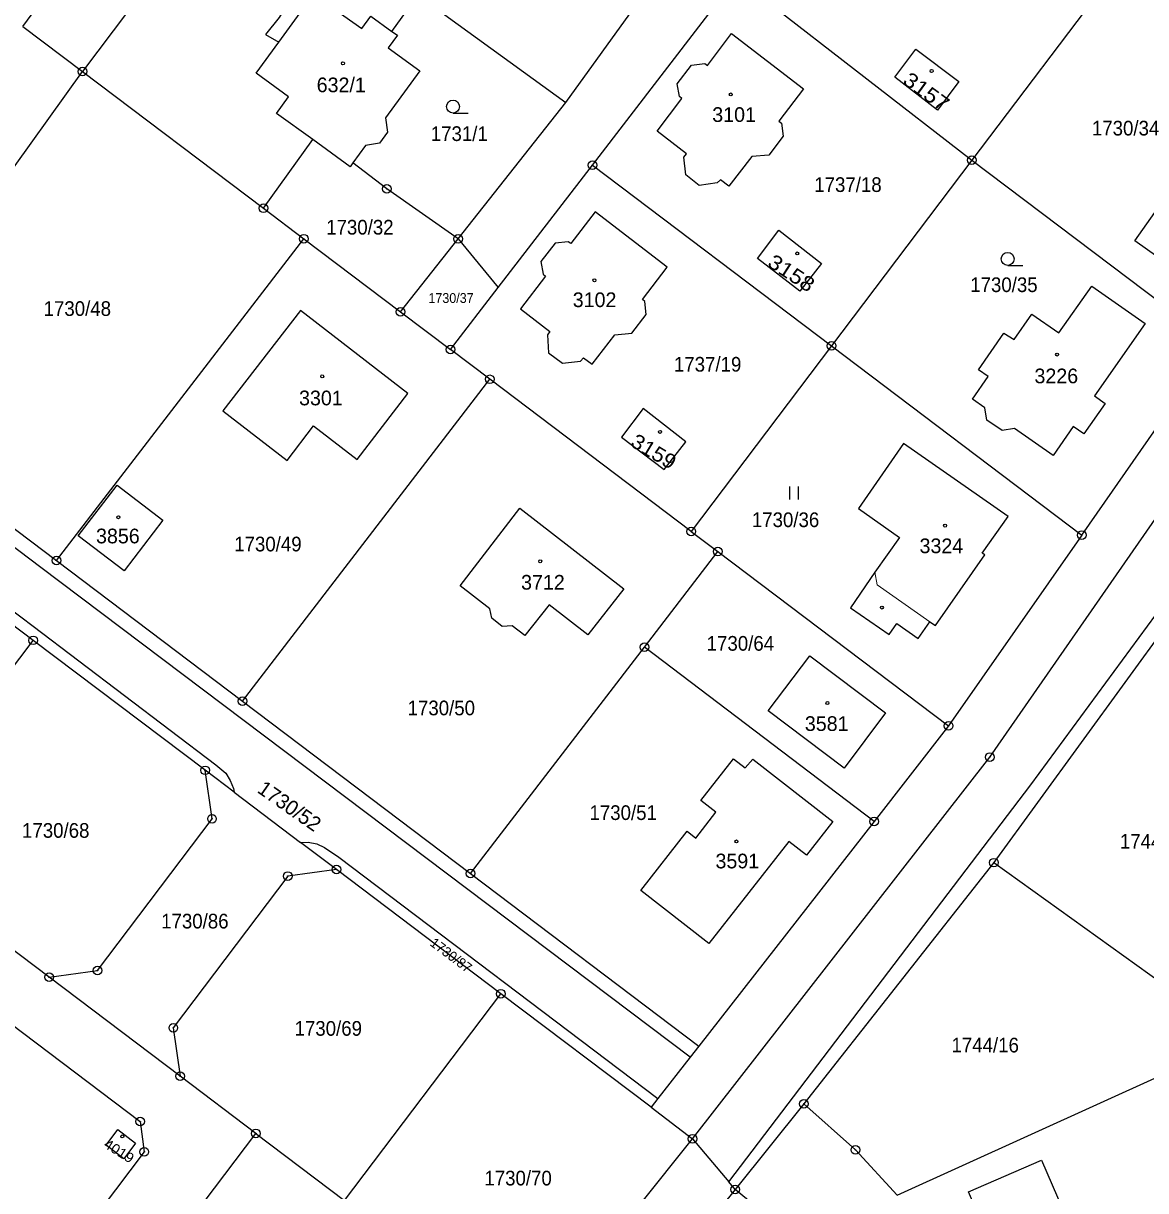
# Model space of a CAD drawing. Extents: x -679733 to -673243, y -1075091 to -1066557.
# Drawn here: x -676982.3 to -676852.3, y -1072340.3 to -1072205.2 of the extents above; entities that cross this region are included whole.
import ezdxf
from ezdxf.enums import TextEntityAlignment as Align

# ---------------------------------------------------------------- set-up
doc = ezdxf.new("R2010")
doc.units = 0
doc.header["$LTSCALE"] = 0.68
for name, color, linetype, lineweight in [('1', 7, 'Continuous', 25), ('3', 7, 'Continuous', 25), ('4', 7, 'Continuous', 13), ('5', 7, 'Continuous', 25), ('8', 7, 'Continuous', 25)]:
    doc.layers.add(name, color=color, linetype=linetype, lineweight=lineweight)
doc.layers.add('2', color=7, linetype='Continuous')

msp = doc.modelspace()

# ---------------------------------------------------------------- linework, layer by layer
at = {"layer": '1'}
for p, q in [((-676899.68, -1072199.86), (-676872.43, -1072221.01)), ((-676934.58, -1072203.37), (-676919.44, -1072214.32)), ((-676982.32, -1072205.52), (-676975.41, -1072210.74)), ((-677002.87, -1072248.9), (-676975.41, -1072210.74)), ((-676931.93, -1072230.12), (-676919.44, -1072214.32)), ((-676916.37, -1072221.57), (-676888.67, -1072242.5)), ((-676954.45, -1072226.57), (-676949.79, -1072230.09)), ((-676888.67, -1072242.5), (-676904.92, -1072263.99)), ((-676904.92, -1072263.99), (-676928.25, -1072246.37)), ((-676961.22, -1072291.64), (-676981.14, -1072276.59)), ((-676883.74, -1072297.55), (-676910.35, -1072277.39)), ((-676956.9, -1072283.63), (-676930.48, -1072303.58)), ((-676957.87, -1072294.17), (-676961.22, -1072291.64)), ((-676946.01, -1072303.12), (-676950.18, -1072299.98)), ((-676869.87, -1072302.33), (-676891.88, -1072330.24)), ((-676930.48, -1072303.58), (-676904.04, -1072323.56)), ((-676909.57, -1072330.65), (-676926.98, -1072317.5)), ((-676891.88, -1072330.24), (-676899.84, -1072340.16)), ((-676955.34, -1072333.67), (-676945.08, -1072341.44)), ((-676904.77, -1072334.29), (-676900.59, -1072339.27)), ((-676899.84, -1072340.16), (-676900.59, -1072339.27))]:
    msp.add_line(p, q, dxfattribs=at)
for points in [[(-676919.44, -1072214.32), (-676899.4, -1072186.54), (-676904.51, -1072167.26)], [(-676982.32, -1072205.52), (-676964.73, -1072181.57), (-676957.44, -1072186.84), (-676936.58, -1072201.92), (-676934.58, -1072203.37)], [(-676957.44, -1072186.84), (-676975.41, -1072210.74), (-676954.45, -1072226.57), (-676948.76, -1072218.62)], [(-676904.77, -1072334.29), (-676870.34, -1072290.1), (-676818.72, -1072215.8), (-676800.09, -1072189.36)], [(-676937.89, -1072203.74), (-676947.59, -1072196.14), (-676952.65, -1072204.47), (-676954.21, -1072206.43), (-676952.7, -1072207.35)], [(-676931.93, -1072230.12), (-676927.27, -1072235.75), (-676916.37, -1072221.57), (-676899.68, -1072199.86)], [(-676952.7, -1072207.35), (-676948.66, -1072201.76), (-676943.09, -1072205.77), (-676942.03, -1072204.31), (-676939.58, -1072206.09), (-676937.89, -1072203.74)], [(-676939.58, -1072206.09), (-676938.96, -1072206.54), (-676940.01, -1072207.99), (-676936.36, -1072210.64), (-676940.32, -1072216.11), (-676940.09, -1072217.74), (-676941.03, -1072219.03), (-676942.65, -1072219.3), (-676944.1, -1072221.31)], [(-676948.76, -1072218.62), (-676952.95, -1072215.6), (-676951.55, -1072213.67), (-676955.29, -1072210.94), (-676952.7, -1072207.35)], [(-676944.1, -1072221.31), (-676944.42, -1072221.76), (-676948.76, -1072218.62)], [(-676872.43, -1072221.01), (-676888.67, -1072242.5), (-676859.7, -1072264.4), (-676844.27, -1072242.28)], [(-676931.93, -1072230.12), (-676940.17, -1072224.32), (-676944.1, -1072221.31)], [(-677002.87, -1072248.9), (-676978.44, -1072267.35), (-676949.79, -1072230.09)], [(-676949.79, -1072230.09), (-676938.6, -1072238.55), (-676931.93, -1072230.12)], [(-676900.59, -1072339.27), (-676865.59, -1072293.33), (-676821.22, -1072232.97)], [(-676938.6, -1072238.55), (-676932.8, -1072242.93), (-676927.27, -1072235.75)], [(-676978.44, -1072267.35), (-676956.9, -1072283.63), (-676928.25, -1072246.37), (-676932.8, -1072242.93)], [(-676905.06, -1072324.86), (-676980.24, -1072268.15), (-677003.21, -1072250.78), (-677011.13, -1072244.77)], [(-677014.68, -1072249.6), (-677006.87, -1072255.49), (-676981.13, -1072274.94), (-676959.99, -1072291), (-676958.83, -1072291.96), (-676958.3, -1072292.81), (-676957.95, -1072293.75), (-676957.87, -1072294.17), (-676950.18, -1072299.98)], [(-677028.33, -1072278.52), (-676999.23, -1072300.52), (-676981.14, -1072276.59), (-677009.25, -1072255.35)], [(-676904.92, -1072263.99), (-676901.84, -1072266.32), (-676875.12, -1072286.5)], [(-676859.7, -1072264.4), (-676875.12, -1072286.5), (-676883.74, -1072297.55), (-676904.04, -1072323.56), (-676905.06, -1072324.86), (-676908.8, -1072329.65), (-676909.57, -1072330.65), (-676904.77, -1072334.29)], [(-676930.48, -1072303.58), (-676910.35, -1072277.39), (-676901.84, -1072266.32)], [(-676844.59, -1072267.57), (-676869.87, -1072302.33), (-676850.33, -1072316.37)], [(-676979.28, -1072315.59), (-676973.68, -1072314.81), (-676960.42, -1072297.25), (-676961.22, -1072291.64)], [(-677027.68, -1072429.42), (-677013.21, -1072410.27), (-676998.74, -1072391.12), (-676984.27, -1072371.97), (-676969.81, -1072352.82), (-676955.34, -1072333.67), (-676964.12, -1072327.04), (-676979.28, -1072315.59), (-676999.23, -1072300.52), (-677013.7, -1072319.67), (-677028.16, -1072338.82), (-677042.63, -1072357.97), (-677057.1, -1072377.12), (-677060.11, -1072381.11), (-677041.76, -1072394.98)], [(-676950.18, -1072299.98), (-676949.27, -1072299.96), (-676948.29, -1072300.16), (-676947.39, -1072300.57), (-676945.74, -1072301.71), (-676908.8, -1072329.65)], [(-676946.01, -1072303.12), (-676951.64, -1072303.88), (-676964.9, -1072321.44), (-676964.12, -1072327.04)], [(-676945.08, -1072341.44), (-676926.98, -1072317.5), (-676946.01, -1072303.12)], [(-677034.04, -1072358.2), (-676999.38, -1072312.31), (-676995.87, -1072311.82), (-676968.74, -1072332.31), (-676968.26, -1072335.81), (-677002.92, -1072381.7)], [(-676891.88, -1072330.24), (-676885.92, -1072335.57), (-676881.09, -1072340.82), (-676850.38, -1072326.91), (-676840.3, -1072323.62), (-676850.33, -1072316.37)], [(-676945.08, -1072341.44), (-676923.5, -1072357.73), (-676904.77, -1072334.29)], [(-676899.84, -1072340.16), (-676917.54, -1072362.22), (-676920.09, -1072365.43), (-676901.39, -1072381.05)], [(-676891.76, -1072389.1), (-676878.69, -1072384.73), (-676876.78, -1072380.9), (-676883.43, -1072361.01), (-676885.57, -1072356.35), (-676888.78, -1072351.13), (-676893.71, -1072345.23), (-676899.84, -1072340.16)]]:
    msp.add_lwpolyline(points, dxfattribs=at)
for points in [[(-676844.27, -1072242.28), (-676829.22, -1072220.7), (-676848.74, -1072205.36), (-676856.19, -1072199.51), (-676872.43, -1072221.01)], [(-676901.53, -1072223.27), (-676901.92, -1072223.61), (-676903.99, -1072223.94), (-676905.55, -1072222.71), (-676905.77, -1072220.66), (-676905.48, -1072220.26), (-676908.89, -1072217.63), (-676906.02, -1072213.86), (-676906.3, -1072213.62), (-676906.56, -1072212.15), (-676904.89, -1072210), (-676903.37, -1072209.8), (-676903.06, -1072210.02), (-676900.26, -1072206.35), (-676891.93, -1072212.75), (-676894.78, -1072216.47), (-676894.48, -1072216.72), (-676894.29, -1072218.2), (-676895.96, -1072220.4), (-676897.9, -1072220.58), (-676900.56, -1072224.01)], [(-676873.92, -1072211.88), (-676876.42, -1072215.19), (-676881.35, -1072211.4), (-676878.9, -1072208.15)], [(-676853.57, -1072230.33), (-676844.23, -1072217.11), (-676837.7, -1072221.73), (-676847.02, -1072234.95)], [(-676921.58, -1072241.22), (-676921.46, -1072243.29), (-676919.84, -1072244.51), (-676917.76, -1072244.27), (-676917.39, -1072243.87), (-676916.41, -1072244.6), (-676913.78, -1072241.23), (-676911.81, -1072241.02), (-676910.14, -1072238.87), (-676910.3, -1072237.35), (-676910.58, -1072237.12), (-676907.73, -1072233.39), (-676916.04, -1072226.98), (-676918.88, -1072230.64), (-676919.16, -1072230.44), (-676920.7, -1072230.61), (-676922.36, -1072232.73), (-676922.09, -1072234.21), (-676921.8, -1072234.44), (-676924.71, -1072238.2), (-676921.29, -1072240.84)], [(-676889.83, -1072232.95), (-676892.35, -1072236.18), (-676897.25, -1072232.37), (-676894.77, -1072229.1)], [(-676870.93, -1072249.66), (-676872.37, -1072248.67), (-676870.56, -1072246.05), (-676871.67, -1072245.26), (-676868.71, -1072241.01), (-676867.53, -1072241.76), (-676865.5, -1072238.84), (-676862.35, -1072240.99), (-676858.55, -1072235.58), (-676852.37, -1072239.9), (-676858.23, -1072248.3), (-676857, -1072249.16), (-676859.45, -1072252.68), (-676860.69, -1072251.83), (-676863.03, -1072255.19), (-676867.49, -1072252.07), (-676868.91, -1072252.31), (-676870.68, -1072251.08)], [(-676950.19, -1072238.42), (-676959.18, -1072250.03), (-676951.72, -1072255.78), (-676948.65, -1072251.77), (-676943.61, -1072255.64), (-676937.73, -1072248.01)], [(-676908.07, -1072256.82), (-676905.56, -1072253.61), (-676910.49, -1072249.76), (-676912.99, -1072253.05)], [(-676870.91, -1072266.7), (-676871.23, -1072266.48), (-676868.22, -1072262.25), (-676880.35, -1072253.8), (-676885.54, -1072261.32), (-676880.82, -1072264.69), (-676883.67, -1072268.69), (-676886.47, -1072272.81), (-676882, -1072275.9), (-676881.11, -1072274.65), (-676878.64, -1072276.36), (-676877.29, -1072274.43), (-676876.63, -1072274.89)], [(-676975.9, -1072264.49), (-676971.42, -1072258.62), (-676966.12, -1072262.67), (-676970.61, -1072268.54)], [(-676926.82, -1072274.99), (-676928, -1072274.03), (-676928.24, -1072272.95), (-676931.7, -1072270.27), (-676924.79, -1072261.29), (-676912.75, -1072270.63), (-676916.9, -1072275.97), (-676921.39, -1072272.46), (-676924.19, -1072276.03), (-676925.67, -1072274.92)], [(-676891.21, -1072278.38), (-676882.42, -1072285), (-676887.23, -1072291.4), (-676896.02, -1072284.77)], [(-676904.4, -1072299.48), (-676902.08, -1072296.5), (-676903.8, -1072295.15), (-676900.03, -1072290.31), (-676898.7, -1072291.34), (-676897.78, -1072290.34), (-676888.52, -1072297.55), (-676891.58, -1072301.47), (-676893.62, -1072299.88), (-676902.88, -1072311.7), (-676910.77, -1072305.54), (-676905.4, -1072298.69)], [(-676971.34, -1072333.24), (-676969.29, -1072334.79), (-676970.62, -1072336.61), (-676972.67, -1072335.03)], [(-676866.54, -1072354.96), (-676869.74, -1072347.57), (-676869.09, -1072347.28), (-676870.37, -1072344.36), (-676871.02, -1072344.64), (-676872.83, -1072340.44), (-676864.36, -1072336.78), (-676858.08, -1072351.31)]]:
    msp.add_lwpolyline(points, close=True, dxfattribs=at)
at = {"layer": '3'}
for p, q in [((-676932.513, -1072215.54), (-676930.763, -1072215.54)), ((-676868.283, -1072233.18), (-676866.533, -1072233.18)), ((-676893.521, -1072260.29), (-676893.521, -1072258.79)), ((-676892.52, -1072260.29), (-676892.52, -1072258.79))]:
    msp.add_line(p, q, dxfattribs=at)
for centre in [(-676932.5129, -1072214.7898), (-676868.2829, -1072232.4298)]:
    msp.add_circle(centre, 0.75, dxfattribs=at)
at = {"layer": '4'}
for p, q in [((-676883.67, -1072268.69), (-676883.4, -1072270.15)), ((-676883.4, -1072270.15), (-676877.29, -1072274.43))]:
    msp.add_line(p, q, dxfattribs=at)
at = {"layer": '5'}
for centre in [(-676945.2568, -1072209.7792), (-676877.0868, -1072210.6792), (-676900.3468, -1072213.3892), (-676892.6568, -1072231.7992), (-676916.1368, -1072234.9092), (-676862.5568, -1072243.4992), (-676947.6568, -1072246.0292), (-676908.5368, -1072252.4592), (-676971.2668, -1072262.3392), (-676875.5268, -1072263.3092), (-676922.4168, -1072267.4392), (-676882.8468, -1072272.7992), (-676889.1568, -1072283.8492), (-676899.6868, -1072299.8692), (-676970.8068, -1072334.0292)]:
    msp.add_circle(centre, 0.175, dxfattribs=at)
at = {"layer": '8'}
for centre, radius in [((-676975.41, -1072210.7399), 0.5), ((-676975.41, -1072210.7399), 0.0303), ((-676872.43, -1072221.0099), 0.5), ((-676872.43, -1072221.0099), 0.0303), ((-676916.37, -1072221.5699), 0.5), ((-676916.37, -1072221.5699), 0.0303), ((-676940.17, -1072224.3199), 0.5), ((-676940.17, -1072224.3199), 0.0303), ((-676954.45, -1072226.5699), 0.5), ((-676954.45, -1072226.5699), 0.0303), ((-676949.79, -1072230.0899), 0.5), ((-676949.79, -1072230.0899), 0.0303), ((-676931.93, -1072230.1199), 0.5), ((-676931.93, -1072230.1199), 0.0303), ((-676938.6, -1072238.5499), 0.5), ((-676938.6, -1072238.5499), 0.0303), ((-676932.8, -1072242.9299), 0.5), ((-676888.67, -1072242.4999), 0.5), ((-676888.67, -1072242.4999), 0.0303), ((-676932.8, -1072242.9299), 0.0303), ((-676928.25, -1072246.3699), 0.5), ((-676928.25, -1072246.3699), 0.0303), ((-676904.92, -1072263.9899), 0.5), ((-676904.92, -1072263.9899), 0.0303), ((-676859.7, -1072264.3999), 0.5), ((-676859.7, -1072264.3999), 0.0303), ((-676978.44, -1072267.3499), 0.5), ((-676901.84, -1072266.3199), 0.5), ((-676901.84, -1072266.3199), 0.0303), ((-676978.44, -1072267.3499), 0.0303), ((-676981.14, -1072276.5899), 0.5), ((-676981.14, -1072276.5899), 0.0303), ((-676910.35, -1072277.3899), 0.5), ((-676910.35, -1072277.3899), 0.0303), ((-676956.9, -1072283.6299), 0.5), ((-676956.9, -1072283.6299), 0.0303), ((-676875.12, -1072286.4999), 0.5), ((-676875.12, -1072286.4999), 0.0303), ((-676870.34, -1072290.0999), 0.5), ((-676961.22, -1072291.6399), 0.5), ((-676870.34, -1072290.0999), 0.0303), ((-676961.22, -1072291.6399), 0.0303), ((-676960.42, -1072297.2499), 0.5), ((-676960.42, -1072297.2499), 0.0303), ((-676883.74, -1072297.5499), 0.5), ((-676883.74, -1072297.5499), 0.0303), ((-676869.87, -1072302.3299), 0.5), ((-676951.64, -1072303.8799), 0.5), ((-676946.01, -1072303.1199), 0.5), ((-676946.01, -1072303.1199), 0.0303), ((-676930.48, -1072303.5799), 0.5), ((-676869.87, -1072302.3299), 0.0303), ((-676951.64, -1072303.8799), 0.0303), ((-676930.48, -1072303.5799), 0.0303), ((-676979.28, -1072315.5899), 0.5), ((-676979.28, -1072315.5899), 0.0303), ((-676973.68, -1072314.8099), 0.5), ((-676973.68, -1072314.8099), 0.0303), ((-676926.98, -1072317.4999), 0.5), ((-676926.98, -1072317.4999), 0.0303), ((-676964.9, -1072321.4399), 0.5), ((-676964.9, -1072321.4399), 0.0303), ((-676964.12, -1072327.0399), 0.5), ((-676964.12, -1072327.0399), 0.0303), ((-676891.88, -1072330.2399), 0.5), ((-676891.88, -1072330.2399), 0.0303), ((-676968.74, -1072332.3099), 0.5), ((-676968.74, -1072332.3099), 0.0303), ((-676955.34, -1072333.6699), 0.5), ((-676955.34, -1072333.6699), 0.0303), ((-676904.77, -1072334.2899), 0.5), ((-676904.77, -1072334.2899), 0.0303), ((-676968.26, -1072335.8099), 0.5), ((-676968.26, -1072335.8099), 0.0303), ((-676885.92, -1072335.5699), 0.5), ((-676885.92, -1072335.5699), 0.0303), ((-676899.84, -1072340.1599), 0.5), ((-676899.84, -1072340.1599), 0.0303)]:
    msp.add_circle(centre, radius, dxfattribs=at)

# ---------------------------------------------------------------- texts
at = {"layer": '2'}
for s, p in [('632/1', (-676948.3, -1072213.13)), ('3101', (-676902.49, -1072216.57)), ('3102', (-676918.65, -1072238.009)), ('3226', (-676865.18, -1072246.83)), ('3301', (-676950.34, -1072249.38)), ('3856', (-676973.85, -1072265.36)), ('3324', (-676878.49, -1072266.499)), ('3712', (-676924.63, -1072270.72)), ('3581', (-676891.77, -1072287.08)), ('3591', (-676902.12, -1072302.989))]:
    msp.add_text(s, height=1.7, dxfattribs=at).set_placement(p)
for s, rotation, width, p in [('3157', 324, 1.15, (-676880.549, -1072212.047)), ('3158', 327, 1.15, (-676896.222, -1072233.202)), ('3159', 329, 1.1, (-676912.087, -1072254.018))]:
    msp.add_text(s, height=1.7, rotation=rotation, dxfattribs=dict(at, width=width)).set_placement(p)
at = {"layer": '2', "width": 0.95}
for s, height, p in [('1730/34', 1.7, (-676858.53, -1072218.14)), ('1731/1', 1.7, (-676935.09, -1072218.779)), ('1737/18', 1.7, (-676890.68, -1072224.68)), ('1730/32', 1.7, (-676947.2, -1072229.61)), ('1730/35', 1.7, (-676872.62, -1072236.269)), ('1730/37', 1.14, (-676935.36, -1072237.53)), ('1730/48', 1.7, (-676979.92, -1072239.029)), ('1737/19', 1.7, (-676906.93, -1072245.479)), ('1730/36', 1.7, (-676897.91, -1072263.479)), ('1730/49', 1.7, (-676957.85, -1072266.29)), ('1730/64', 1.7, (-676903.14, -1072277.79)), ('1730/50', 1.7, (-676937.77, -1072285.269)), ('1730/51', 1.7, (-676916.71, -1072297.39)), ('1730/68', 1.7, (-676982.42, -1072299.45)), ('1744/15', 1.7, (-676855.29, -1072300.72)), ('1730/86', 1.7, (-676966.31, -1072309.95)), ('1730/69', 1.7, (-676950.86, -1072322.37)), ('1744/16', 1.7, (-676874.79, -1072324.3)), ('1730/70', 1.7, (-676928.88, -1072339.7))]:
    msp.add_text(s, height=height, dxfattribs=at).set_placement(p)
at = {"layer": '2'}
for s, height, rotation, p in [('1730/52', 1.7, 325, (-676955.297, -1072294.116)), ('1730/87', 1.14, 323, (-676935.273, -1072311.835))]:
    msp.add_text(s, height=height, rotation=rotation, dxfattribs=at).set_placement(p)
at = {"layer": '2', "width": 1.1}
msp.add_text('4019', height=1.14, rotation=328, dxfattribs=at).set_placement((-676971.4896, -1072336.1989), align=Align.CENTER)

doc.saveas('drawing.dxf')
